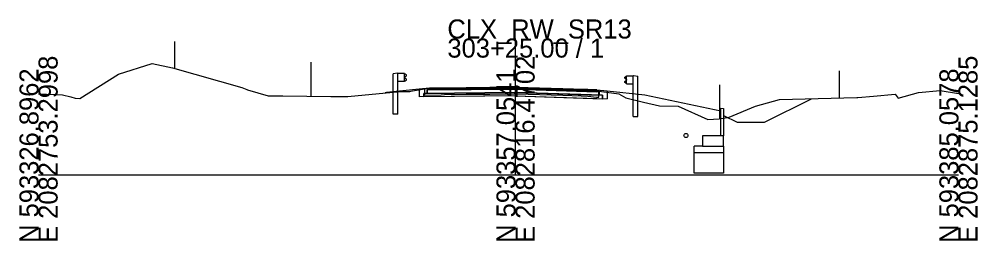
# Model space of a CAD drawing. Extents: x -26 to 2138, y -10 to 4518.
# Drawn here: x 997.2 to 1137.8, y 1990.3 to 2022.8 of the extents above; entities that cross this region are included whole.
import ezdxf

# ---------------------------------------------------------------- set-up
doc = ezdxf.new("R2010")
doc.units = 0
for name, color, linetype in [('GK_Cells', 7, 'Continuous'), ('MD_P_Surface_Aggregate_Base', 7, 'Continuous'), ('MD_P_Surface_Asphalt_Concrete_Base', 7, 'Continuous'), ('MD_P_Surface_Asphalt_Concrete_Intermediate_Course', 7, 'Continuous'), ('MD_P_Surface_Asphalt_Concrete_Surface_Course', 7, 'Continuous'), ('MD_P_Surface_Non-Reinforced_Concrete_Pavement', 7, 'Continuous'), ('MD_X_Asphalt_Pavement', 7, 'Continuous'), ('RD_P_Cells', 7, 'Continuous'), ('RW_P_Esmt_SH', 7, 'Continuous'), ('RW_X_Esmt_SH', 7, 'Continuous'), ('SC_Scratch1', 7, 'Continuous'), ('UT_X_Water', 7, 'Continuous'), ('XS_P_Excavation_Limits', 7, 'Continuous'), ('XS_P_Finished_Grade', 7, 'Continuous'), ('XS_P_Subgrade', 7, 'Continuous'), ('XS_X_Ground_Line', 7, 'Continuous')]:
    doc.layers.add(name, color=color, linetype=linetype)

msp = doc.modelspace()

# ---------------------------------------------------------------- linework, layer by layer
at = {"layer": 'GK_Cells'}
for p, q in [((1070, 2000), (1070, 2020)), ((1000, 2000), (1070, 2000)), ((1070, 2000), (1135, 2000))]:
    msp.add_line(p, q, dxfattribs=at)
at = {"layer": 'MD_P_Surface_Aggregate_Base'}
for points in [[(1070, 2012.08), (1070, 2011.58), (1056.53, 2011.45), (1056.53, 2011.95), (1070, 2012.08)], [(1070, 2012.08), (1070, 2011.58), (1082.77, 2011.17), (1082.77, 2011.67), (1070, 2012.08)]]:
    msp.add_lwpolyline(points, dxfattribs=at)
at = {"layer": 'MD_P_Surface_Asphalt_Concrete_Base'}
for points in [[(1070, 2012.58), (1070, 2012.08), (1057.03, 2011.95), (1057.03, 2012.45), (1070, 2012.58)], [(1070, 2012.58), (1070, 2012.08), (1082.27, 2011.68), (1082.27, 2012.18), (1081.94, 2012.2), (1070, 2012.58)]]:
    msp.add_lwpolyline(points, dxfattribs=at)
at = {"layer": 'MD_P_Surface_Asphalt_Concrete_Intermediate_Course'}
for points in [[(1070, 2012.73), (1070, 2012.58), (1057.36, 2012.45), (1057.36, 2012.6), (1070, 2012.73)], [(1070, 2012.73), (1070, 2012.58), (1081.94, 2012.2), (1081.94, 2012.34), (1070, 2012.73)]]:
    msp.add_lwpolyline(points, dxfattribs=at)
at = {"layer": 'MD_P_Surface_Asphalt_Concrete_Surface_Course'}
for points in [[(1070, 2012.83), (1070, 2012.73), (1057.36, 2012.6), (1057.36, 2012.7), (1070, 2012.83)], [(1070, 2012.83), (1070, 2012.73), (1081.94, 2012.34), (1081.94, 2012.45), (1070, 2012.83)]]:
    msp.add_lwpolyline(points, dxfattribs=at)
at = {"layer": 'MD_P_Surface_Non-Reinforced_Concrete_Pavement'}
for points in [[(1100.53, 2009.72), (1100.53, 2005.72), (1100.11, 2005.72), (1100.11, 2009.8), (1100.53, 2009.72)], [(1098.68, 2005.72), (1097.46, 2005.72), (1097.46, 2005.65), (1097.46, 2004.22), (1098.57, 2004.22), (1099.01, 2004.22), (1099.7, 2004.22), (1100.53, 2004.22), (1100.53, 2004.61), (1100.53, 2005.72), (1099.91, 2005.72), (1099.01, 2005.72), (1098.68, 2005.72)]]:
    msp.add_lwpolyline(points, dxfattribs=at)
at = {"layer": 'MD_X_Asphalt_Pavement'}
msp.add_lwpolyline([(1059.07, 2012.68), (1056.64, 2012.62), (1056.64, 2011.67), (1059.07, 2011.73), (1059.57, 2011.77), (1062.75, 2011.81), (1066.23, 2011.84), (1069.82, 2011.87), (1070.15, 2011.87), (1076.93, 2011.67), (1079.61, 2011.57), (1080.59, 2011.54), (1081.89, 2011.4), (1081.93, 2011.39), (1082.21, 2011.38), (1082.21, 2012.34), (1081.93, 2012.35), (1081.89, 2012.35), (1080.59, 2012.5), (1079.61, 2012.53), (1076.93, 2012.63), (1070.15, 2012.83), (1069.82, 2012.83), (1066.23, 2012.8), (1062.75, 2012.76), (1059.57, 2012.73), (1059.07, 2012.68)], dxfattribs=at)
at = {"layer": 'RD_P_Cells'}
for p, q in [((1052.1, 2014.83), (1052.05, 2014.81)), ((1052.05, 2008.91), (1052.05, 2014.81)), ((1052.64, 2014.91), (1052.1, 2014.83)), ((1052.72, 2014.87), (1052.64, 2014.91)), ((1053.72, 2014.87), (1052.72, 2014.87)), ((1052.72, 2008.91), (1052.72, 2014.87)), ((1053.72, 2013.68), (1053.72, 2014.87)), ((1053.81, 2014.77), (1053.72, 2014.78)), ((1053.97, 2014.66), (1053.81, 2014.77)), ((1087.28, 2014.54), (1087.36, 2014.58)), ((1087.36, 2014.58), (1087.9, 2014.5)), ((1053.72, 2013.68), (1052.72, 2013.68)), ((1053.72, 2013.76), (1053.81, 2013.78)), ((1053.73, 2014.27), (1053.73, 2014.32)), ((1053.73, 2014.23), (1053.73, 2014.27)), ((1053.76, 2014.38), (1053.97, 2014.53)), ((1053.97, 2014.02), (1053.76, 2014.16)), ((1053.81, 2013.78), (1053.97, 2013.89)), ((1086.03, 2014.33), (1086.19, 2014.44)), ((1086.24, 2014.05), (1086.03, 2014.2)), ((1086.03, 2013.69), (1086.24, 2013.83)), ((1086.19, 2013.45), (1086.03, 2013.56)), ((1086.19, 2014.44), (1086.28, 2014.45)), ((1086.28, 2013.43), (1086.19, 2013.45)), ((1086.27, 2013.94), (1086.27, 2013.99)), ((1086.27, 2013.9), (1086.27, 2013.94)), ((1086.28, 2013.35), (1086.28, 2014.54)), ((1086.28, 2014.54), (1087.28, 2014.54)), ((1086.28, 2013.35), (1087.28, 2013.35)), ((1087.28, 2008.58), (1087.28, 2014.54)), ((1087.9, 2014.5), (1087.95, 2014.48)), ((1087.95, 2008.58), (1087.95, 2014.48)), ((1052.72, 2008.91), (1052.05, 2008.91)), ((1087.28, 2008.58), (1087.95, 2008.58))]:
    msp.add_line(p, q, dxfattribs=at)
for points in [[(1053.74, 2014.33), (1053.74, 2014.21), (1053.73, 2014.21), (1053.73, 2014.33)], [(1053.74, 2014.3), (1053.74, 2014.24), (1053.76, 2014.24), (1053.76, 2014.3)], [(1086.26, 2013.97), (1086.26, 2013.91), (1086.24, 2013.91), (1086.24, 2013.97)], [(1086.26, 2014), (1086.26, 2013.88), (1086.27, 2013.88), (1086.27, 2014)]]:
    msp.add_lwpolyline(points, close=True, dxfattribs=at)
for centre, start, end in [((1053.92, 2014.59), 304.962, 54.7677), ((1053.81, 2014.32), 124.962, 180), ((1053.81, 2014.23), 180, 235.038), ((1053.92, 2013.96), 304.962, 54.7677), ((1086.08, 2014.26), 125.2323, 235.038), ((1086.08, 2013.63), 125.2323, 235.038), ((1086.19, 2013.99), 0, 55.038), ((1086.19, 2013.9), 304.962, 0)]:
    msp.add_arc(centre, 0.0781, start, end, dxfattribs=at)
at = {"layer": 'RW_P_Esmt_SH'}
for p, q in [((1020, 2015.58), (1020, 2019.58)), ((1117.56, 2011.27), (1117.56, 2015.27))]:
    msp.add_line(p, q, dxfattribs=at)
at = {"layer": 'RW_X_Esmt_SH'}
for p, q in [((1040, 2011.52), (1040, 2016.52)), ((1100, 2008.22), (1100, 2013.22))]:
    msp.add_line(p, q, dxfattribs=at)
at = {"layer": 'SC_Scratch1'}
for p, q in [((1057.36, 2012.7), (1055.86, 2012.55)), ((1070, 2012.08), (1056.53, 2011.95)), ((1056.53, 2011.95), (1056.53, 2011.45)), ((1070, 2012.58), (1057.03, 2012.45)), ((1057.03, 2012.45), (1057.03, 2011.95)), ((1070, 2012.83), (1057.36, 2012.7)), ((1070, 2012.73), (1057.36, 2012.6)), ((1057.36, 2012.7), (1057.36, 2012.45)), ((1070, 2012.83), (1081.94, 2012.45)), ((1070, 2012.73), (1081.94, 2012.34)), ((1070, 2012.58), (1082.27, 2012.18)), ((1070, 2012.08), (1082.77, 2011.67)), ((1081.94, 2012.45), (1081.94, 2012.2)), ((1081.94, 2012.45), (1083.44, 2012.3)), ((1082.27, 2012.18), (1082.27, 2011.68)), ((1082.77, 2011.67), (1082.77, 2011.17))]:
    msp.add_line(p, q, dxfattribs=at)
at = {"layer": 'UT_X_Water'}
msp.add_circle((1095, 2005.77), 0.3, dxfattribs=at)
at = {"layer": 'XS_P_Excavation_Limits'}
for p, q in [((1096.19, 2000.22), (1096.19, 2004.22)), ((1097.46, 2004.22), (1096.19, 2004.22)), ((1100.53, 2004.22), (1100.53, 2000.22)), ((1100.53, 2003.22), (1096.19, 2003.22)), ((1100.53, 2000.22), (1096.19, 2000.22))]:
    msp.add_line(p, q, dxfattribs=at)
at = {"layer": 'XS_P_Finished_Grade'}
for p, q in [((1051.05, 2012.07), (1050.85, 2012.01)), ((1055.86, 2012.55), (1051.05, 2012.07)), ((1083.44, 2012.3), (1088.95, 2011.74)), ((1088.95, 2011.74), (1100.11, 2009.4)), ((1106.53, 2007.72), (1113.43, 2011.17)), ((1100.53, 2008.72), (1102.53, 2007.72)), ((1102.53, 2007.72), (1106.53, 2007.72))]:
    msp.add_line(p, q, dxfattribs=at)
at = {"layer": 'XS_P_Subgrade'}
for p, q in [((1055.86, 2012.55), (1055.86, 2011.44)), ((1083.44, 2012.3), (1083.44, 2011.15)), ((1070, 2011.58), (1055.86, 2011.44)), ((1070, 2011.58), (1083.44, 2011.15))]:
    msp.add_line(p, q, dxfattribs=at)
at = {"layer": 'XS_X_Ground_Line'}
msp.add_lwpolyline([(1000, 2011.87), (1003.51, 2011.72), (1004.73, 2011.42), (1005.37, 2011.27), (1006.08, 2011.22), (1011.71, 2014.78), (1016.66, 2016.34), (1019.64, 2015.68), (1029.84, 2012.82), (1030.58, 2012.51), (1030.68, 2012.49), (1033.7, 2011.61), (1035.83, 2011.58), (1042.91, 2011.48), (1045.4, 2011.49), (1053.08, 2012.22), (1054.48, 2012.23), (1054.63, 2012.28), (1054.9, 2012.31), (1056.64, 2012.62), (1059.07, 2012.68), (1059.57, 2012.73), (1066.23, 2012.8), (1070.15, 2012.83), (1076.93, 2012.63), (1080.59, 2012.5), (1081.93, 2012.35), (1082.21, 2012.34), (1082.25, 2012.29), (1082.62, 2012.23), (1085.16, 2011.87), (1086.2, 2011.29), (1088.8, 2010.64), (1091.14, 2010.11), (1093.87, 2010.08), (1098.22, 2008.14), (1099.9, 2008.2), (1101.35, 2008.47), (1105.19, 2010.07), (1108.73, 2011.05), (1120.09, 2011.34), (1120.24, 2011.35), (1122.52, 2011.55), (1125.69, 2011.84), (1126.14, 2011.24), (1129.14, 2012.08), (1132.3, 2012.36), (1135, 2011.91)], dxfattribs=at)

# ---------------------------------------------------------------- texts
msp.add_text('-', height=0.0001).set_placement((1000, 2000))
at = {"layer": 'GK_Cells'}
for s, p in [('CLX_RW_SR13', (1060, 2020)), ('303+25.00 / 1', (1060, 2017.2))]:
    msp.add_text(s, height=2.8, dxfattribs=at).set_placement(p)
for s, p in [('E 2082753.2998', (1002.8, 1990)), ('E 2082816.4702', (1072.8, 1990)), ('E 2082875.1285', (1137.8, 1990)), ('N 593326.8962', (1000, 1990)), ('N 593357.0541', (1070, 1990)), ('N 593385.0578', (1135, 1990))]:
    msp.add_text(s, height=2.8, rotation=90, dxfattribs=at).set_placement(p)

doc.saveas('drawing.dxf')
